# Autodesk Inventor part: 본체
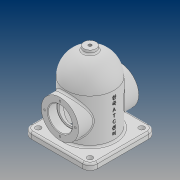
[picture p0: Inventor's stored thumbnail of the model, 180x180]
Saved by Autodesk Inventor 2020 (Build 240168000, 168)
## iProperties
Created: 2021-08
Part Number: 본체
Material: 일반
Document SubType Name: Modeling
Designer: PC312-
Density: 1 g/cm^3
Appearance: 기본값
Mass: 320.706 g
Surface Area: 800.755 cm^2
Volume: 320.706 cm^3
Author: PC312-
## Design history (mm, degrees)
sketch "스케치1"
  geometry: L1 (-42, 0)-(42, 0); L2 (-42, 0)-(-42, 40); L3 (-42, 40)-(42, 40); L4 (42, 0)-(82, 0); L5 (-42, 0)-(82, 0); A1 r 40 centre (42, 0) between (82, 0) and (2, 0); 4 further points
  constraints: 10 end point, 4 horizontal, 2 coincident, 2 midpoint, 2 point on circle, 1 centre point, 1 point on line, 1 vertical, 1 vertical alignment
  dimensions: "d0" = 80 diameter of L3 L1; "d1" = 84 distance of L2.end L3.end; "d2" = 80 diameter of A1
revolve "회전1" sketch "스케치1" stored, may be unused: angle "d3" = 90 deg
feature "쉘1" dims "d4" = 8
sketch "스케치2"
  geometry: L1 (-43, 55)-(43, 55); L2 (55, 43)-(55, -43); L3 (43, -55)-(-43, -55); L4 (-55, -43)-(-55, 43); L5 (-55, 55)-(55, -55); L6 (55, 55)-(-55, -55); C1 r 40 at (0, 0) reference; C2 r 4.5 at (-43, -43); C3 r 4.5 at (43, -43); C4 r 4.5 at (43, 43); C5 r 4.5 at (-43, 43); A1 r 12 centre (-43, -43) between (-55, -43) and (-43, -55); A2 r 12 centre (-43, 43) between (-43, 55) and (-55, 43); A3 r 12 centre (43, 43) between (55, 43) and (43, 55); A4 r 12 centre (43, -43) between (43, -55) and (55, -43); 1 further point
  constraints: 12 end point, 8 centre point, 8 point on circle, 8 point on line, 8 tangent, 4 coincident, 3 equal radius, 2 midpoint, 2 parallel, 1 horizontal, 1 perpendicular
  dimensions: "d6" = 110 distance of L6.start L5.end; "d7" = 110 distance of L5.start L6.start; "d10" = 12 radius of A1; "d11" = 9 diameter of C2; "d12" = 9 diameter of C3; "d13" = 9 diameter of C4; "d14" = 9 diameter of C5
extrude "돌출1" join sketch "스케치2" distance "d8" = 10; taper "d9" = 0 deg
node "작업 평면1"
sketch "스케치3"
  geometry: L1 (43, -42)-(-43, -42) reference; C1 r 31 at (0, 6); 1 further point
  constraints: 1 centre point, 1 vertical alignment
  dimensions: "d15" = 62 diameter of C1; "d16" = 48 distance from line of L1 C1.centre
extrude "돌출2" join sketch "스케치3" stored distance "d17" = 10; taper "d18" = 0 deg
sketch "스케치4"
  geometry: C1 r 31 at (0, 0) reference; C2 r 20 at (0, 0); 1 further point
  constraints: 1 centre point, 1 coincident
  dimensions: "d19" = 40 diameter of C2
extrude "돌출3" cut sketch "스케치4" distance "d20" = 15; taper "d21" = 0 deg
sketch "스케치5"
  geometry: C1 r 20 at (0, 0) reference; C2 r 16.5 at (0, 0); 1 further point
  constraints: 1 centre point, 1 coincident
  dimensions: "d22" = 33 diameter of C2
extrude "돌출4" cut sketch "스케치5" stored distance "d23" = 15; taper "d24" = 0 deg
sketch "스케치6"
  geometry: C1 r 31 at (0, 0) reference; 2 further points
  constraints: 1 vertical alignment
  dimensions: "d29" = 25.5 distance of C1.centre point (0, 25.5)
hole "구멍1" sketch "스케치6" at (0, 25.5) diameter "d30" = 3.242; stored, may be unused: countersink angle "d34" = 90 deg, drill point angle "d36" = 118 deg; dims "d31" = 8, "d32" = 4, "d33" = 2, "d35" = 10
fillet "모깎기1" dims "d25" = 0.3
chamfer "모따기1" distance "d26" = 1; stored, may be unused: second distance "d27" = 2, angle "d28" = 45 deg
node "작업 평면2"
sketch "스케치7"
  geometry: C1 r 10 at (43, -55); 1 further point
  constraints: 1 centre point, 1 coincident
  dimensions: "d41" = 20 diameter of C1
extrude "돌출5" join sketch "스케치7" stored distance "d42" = 15; taper "d43" = 0 deg
sketch "스케치8"
  geometry: C1 r 10 at (0, 0) reference; 2 further points
  constraints: 1 coincident
hole "구멍2" sketch "스케치8" at (0, 0) diameter "d44" = 5.1881; stored, may be unused: countersink angle "d48" = 90 deg, drill point angle "d50" = 0 deg; dims "d45" = 15, "d46" = 4, "d47" = 2, "d49" = 16
fillet "모깎기2" dims "d51" = 3
node "작업 평면3"
sketch "스케치9"
  geometry: L1 (-42, -43)-(-42, 43) reference; 2 further points
  constraints: 1 horizontal alignment, 1 other
  dimensions: "d53" = 48 distance from line of L1 point (6, 0)
feature "엠보싱1" sketch "스케치9" dims "d0" = 80, "d10" = 12, "d54" = 0.5, "d55" = 0
node "솔리드1"
pattern_circular "원형 패턴1" dims angle "d38" = 360 deg
mirror "미러1"
node "투영된 루프1"
feature "A9D066F2-1C7D-4E18-AEED-F7BC21143FA4" dims "d30" = 3.242, "d31" = 8, "d32" = 4, "d33" = 2, "d34" = 90 deg, "d35" = 10, "d36" = 118 deg
other parameters: "d40" = -129
